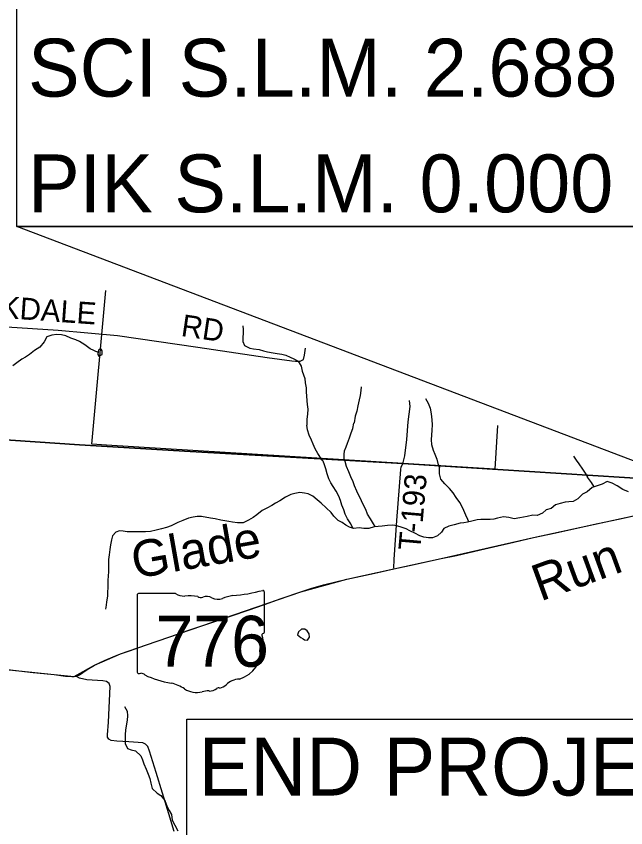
# Model space of a CAD drawing. Extents: x 0 to 40.8, y 0 to 22.
# Drawn here: x 5.177 to 6.756, y 16.222 to 18.326 of the extents above; entities that cross this region are included whole.
import ezdxf

# ---------------------------------------------------------------- set-up
doc = ezdxf.new("R2010")
doc.units = 0
for name, color, linetype in [('Default', 7, 'Continuous'), ('GM_X_County_Road', 7, 'Continuous'), ('GM_X_County_Road_Text', 7, 'Continuous'), ('GM_X_Minor_Lake', 7, 'Continuous'), ('GM_X_Minor_River', 7, 'Continuous'), ('GM_X_Minor_River_Text', 7, 'Continuous'), ('GM_X_Section', 7, 'Continuous'), ('GM_X_State_Location', 7, 'Continuous'), ('GM_X_State_Route', 7, 'Continuous'), ('GM_X_State_Shield', 7, 'Continuous'), ('GM_X_Township_Road', 7, 'Continuous'), ('GM_X_Township_Road_Text', 7, 'Continuous'), ('SH_Cut_Line', 7, 'Continuous')]:
    doc.layers.add(name, color=color, linetype=linetype)

msp = doc.modelspace()

# ---------------------------------------------------------------- linework, layer by layer
at = {"layer": 'Default'}
for points in [[(7.7204, 20.9), (3.6829, 20.9), (3.6703, 20.6733), (3.6672, 20.5588), (3.6386, 20.2396), (3.575, 19.3064), (3.5742, 19.2945), (3.5638, 19.132), (3.4481, 17.3334), (4.5348, 17.2687), (4.8294, 17.2493), (5.3407, 17.2146), (5.6278, 17.197), (6.1785, 17.166), (6.9172, 17.1197)], [(4.3506, 16.715), (5.2748, 16.619), (5.3265, 16.6142), (5.3792, 16.6434), (5.447, 16.6726), (5.5144, 16.6961), (5.9138, 16.8341), (6.0334, 16.8664), (6.155, 16.8931), (6.2776, 16.9198), (6.5168, 16.9746), (6.7757, 17.0304), (6.8501, 17.0497), (6.8977, 17.0853), (6.8977, 17.0853), (6.9174, 17.1192), (6.9291, 17.1755), (6.9382, 17.2349), (6.9766, 17.6024), (7.3436, 17.5605), (7.48, 17.5474)]]:
    msp.add_lwpolyline(points, dxfattribs=at)
for points in [[(5.1786, 18.9041), (6.7762, 18.9041), (6.7762, 17.7808), (5.1786, 17.7808)], [(6.7762, 17.7808), (6.9172, 17.1197), (5.1786, 17.7808)], [(2.1, 16.4387), (2.1, 14.1), (8.9, 14.1), (8.9, 16.9831), (7.7161, 17.0658), (7.7144, 17.066), (7.54, 17.0745), (7.4495, 17.0841), (6.9172, 17.1197), (6.1785, 17.166), (5.6278, 17.197), (5.3407, 17.2146), (4.8294, 17.2493), (4.5348, 17.2687), (3.4481, 17.3334), (3.1244, 17.3534), (2.8484, 17.3691), (2.8463, 17.3693), (2.4594, 17.3966), (2.4379, 17.0913), (2.3911, 16.4258)], [(5.6188, 16.5037), (6.9829, 16.5037), (6.9829, 15.6724), (5.6188, 15.6724)]]:
    msp.add_lwpolyline(points, close=True, dxfattribs=at)
at = {"layer": 'GM_X_County_Road'}
for points in [[(4.8531, 17.7162), (4.8463, 17.5982), (4.8448, 17.577), (4.8443, 17.5626), (4.8478, 17.5533), (4.8489, 17.5499), (4.8504, 17.5469), (4.8523, 17.5442), (4.855, 17.5415), (4.8599, 17.5377), (4.866, 17.535), (4.9121, 17.5364), (5.285, 17.5118), (5.4395, 17.4984), (5.6472, 17.4678), (5.8268, 17.441), (5.8904, 17.4325), (5.9002, 17.4317), (5.9067, 17.4313), (5.9128, 17.4316), (5.9208, 17.4358), (5.9239, 17.4468), (5.9261, 17.4652)], [(6.1787, 17.1655), (6.184, 17.1862), (6.1885, 17.2284), (6.1921, 17.2746), (6.1975, 17.314), (6.1953, 17.3293)], [(5.5855, 16.2123), (5.5718, 16.2585), (5.5392, 16.3655), (5.522, 16.4211), (5.518, 16.4327), (5.5117, 16.4392), (5.5046, 16.4425), (5.4684, 16.4449), (5.4371, 16.4469), (5.4228, 16.448), (5.4163, 16.4517), (5.4135, 16.4569), (5.4132, 16.4633), (5.4156, 16.4956), (5.4205, 16.5879), (5.4171, 16.5964), (5.4104, 16.601), (5.4007, 16.6033), (5.3593, 16.6059), (5.3409, 16.6099), (5.3315, 16.6151)]]:
    msp.add_lwpolyline(points, dxfattribs=at)
at = {"layer": 'GM_X_Minor_Lake'}
for points in [[(5.3883, 17.4487), (5.3905, 17.4449), (5.3943, 17.446), (5.3993, 17.449), (5.3993, 17.4581), (5.3967, 17.4623), (5.3925, 17.462), (5.3899, 17.4601), (5.3887, 17.4563)], [(5.3887, 17.4563), (5.3883, 17.4487)], [(5.9249, 16.7365), (5.9162, 16.7365), (5.9082, 16.7304), (5.9055, 16.7225), (5.9142, 16.7153), (5.9201, 16.7116)], [(5.9201, 16.7116), (5.9233, 16.7096), (5.9317, 16.708), (5.9366, 16.716), (5.9355, 16.7247), (5.9302, 16.7327), (5.9249, 16.7365)]]:
    msp.add_lwpolyline(points, dxfattribs=at)
at = {"layer": 'GM_X_Minor_River'}
for points in [[(5.7639, 17.5235), (5.765, 17.514), (5.765, 17.5034), (5.7638, 17.4939), (5.7641, 17.4829), (5.7682, 17.4723), (5.7818, 17.4654), (5.7916, 17.4634), (5.806, 17.4614), (5.8177, 17.4583), (5.8275, 17.456), (5.8423, 17.4529), (5.8525, 17.4513), (5.8649, 17.4493), (5.8755, 17.4474), (5.8861, 17.442), (5.8959, 17.4378), (5.9069, 17.4316), (5.9151, 17.4187), (5.9177, 17.4054), (5.9214, 17.3959), (5.9244, 17.3864), (5.9254, 17.375), (5.928, 17.3621), (5.9283, 17.3515), (5.929, 17.3413), (5.9293, 17.3291), (5.9304, 17.3189), (5.9322, 17.3071), (5.9318, 17.2946), (5.9298, 17.2813), (5.9293, 17.266)], [(5.3886, 17.4538), (5.3679, 17.4633), (5.3547, 17.4739), (5.3408, 17.4828), (5.331, 17.487), (5.3185, 17.4912), (5.3049, 17.497), (5.294, 17.4997), (5.2815, 17.5005), (5.2693, 17.4987), (5.2564, 17.4946), (5.2488, 17.4818), (5.2381, 17.4674), (5.224, 17.4592), (5.2107, 17.449), (5.2005, 17.4423), (5.191, 17.4366), (5.178, 17.4272), (5.1681, 17.4197)], [(6.0704, 17.3654), (6.0699, 17.3552), (6.068, 17.3423), (6.0656, 17.331), (6.0621, 17.3158), (6.0594, 17.3018), (6.0551, 17.2886), (6.0519, 17.272)], [(6.2375, 17.3345), (6.2439, 17.3227), (6.2491, 17.3094), (6.2517, 17.295), (6.2535, 17.2798), (6.2541, 17.2669), (6.2533, 17.2525), (6.2516, 17.2275), (6.2523, 17.2154), (6.2568, 17.2009), (6.2616, 17.1903), (6.2668, 17.1774), (6.2687, 17.166), (6.2737, 17.1555)], [(6.0286, 17.1711), (6.0268, 17.1783), (6.0264, 17.1893), (6.0276, 17.1988), (6.0314, 17.2098), (6.0352, 17.2193), (6.0405, 17.2329), (6.0447, 17.2454), (6.0489, 17.2572), (6.0512, 17.2705), (6.0519, 17.272)], [(5.9697, 17.1749), (5.9579, 17.1921), (5.9515, 17.2042), (5.9458, 17.2168), (5.942, 17.227), (5.936, 17.2395), (5.9311, 17.2532), (5.9293, 17.266)], [(6.6205, 17.1855), (6.6276, 17.1753), (6.6348, 17.1657), (6.6438, 17.1517), (6.6509, 17.1414), (6.6566, 17.1311)], [(6.0492, 16.9986), (6.044, 17.0103), (6.0353, 17.0229), (6.0293, 17.0354), (6.0258, 17.046), (6.0205, 17.0581), (6.0168, 17.0703), (6.0122, 17.0817), (6.0061, 17.0942), (5.9978, 17.1071), (5.9918, 17.1166), (5.9868, 17.1264), (5.9823, 17.1397), (5.9785, 17.1526), (5.9755, 17.1625), (5.9717, 17.172), (5.9697, 17.1749)], [(6.1067, 17.0026), (6.102, 17.0103), (6.0944, 17.0225), (6.0872, 17.035), (6.0823, 17.0475), (6.0743, 17.0631), (6.0683, 17.076), (6.0634, 17.0855), (6.0596, 17.0949), (6.0535, 17.1086), (6.0497, 17.1185), (6.0437, 17.1321), (6.0387, 17.145), (6.0323, 17.1583), (6.0286, 17.1711)], [(6.3494, 17.015), (6.3464, 17.0213), (6.3414, 17.0327), (6.3365, 17.0448), (6.3312, 17.0555), (6.3263, 17.065), (6.3164, 17.0779), (6.3085, 17.09), (6.299, 17.1018), (6.2876, 17.1139), (6.2767, 17.1257), (6.2736, 17.1393), (6.2737, 17.1555)], [(6.6745, 17.1061), (6.6669, 17.1173), (6.6566, 17.1311)], [(6.7631, 17.093), (6.7487, 17.0991), (6.7339, 17.1082), (6.7211, 17.1154), (6.7082, 17.1196), (6.6949, 17.1131), (6.682, 17.1086), (6.6692, 17.1044), (6.6563, 17.0926), (6.6442, 17.0869), (6.6316, 17.0744), (6.6199, 17.068), (6.6089, 17.0668), (6.5991, 17.0661), (6.5862, 17.0623), (6.5741, 17.0596), (6.5631, 17.0498), (6.5498, 17.046), (6.5403, 17.0373), (6.5263, 17.0319), (6.5153, 17.0323), (6.5006, 17.0293), (6.4911, 17.027), (6.4816, 17.0251), (6.4668, 17.0225), (6.4528, 17.0266), (6.4396, 17.0278), (6.424, 17.0244), (6.4142, 17.0221), (6.4043, 17.0209), (6.3808, 17.0209), (6.371, 17.0202), (6.3573, 17.0168), (6.3456, 17.0141), (6.3361, 17.0122), (6.3267, 17.0115), (6.3115, 17.0077), (6.2975, 17.0039), (6.285, 16.9982), (6.2785, 16.9883), (6.2683, 16.9792), (6.2554, 16.9735), (6.2452, 16.9739), (6.2327, 16.9758), (6.2228, 16.9792), (6.2096, 16.9861)], [(6.2096, 16.9861), (6.1967, 16.9917), (6.1872, 16.9971), (6.177, 17.0008), (6.1626, 17.005), (6.1524, 17.0065), (6.1391, 17.0058), (6.1247, 17.0039), (6.1141, 17.0031), (6.1043, 17.0024), (6.0902, 16.9978), (6.0777, 16.9982), (6.0649, 16.9997), (6.0505, 16.9982), (6.0406, 17.0012), (6.0311, 17.0069), (6.0209, 17.013), (6.0111, 17.0183), (5.9997, 17.0297), (5.9925, 17.0396), (5.98, 17.0517), (5.9664, 17.0638), (5.9565, 17.0722), (5.9455, 17.0817), (5.9334, 17.0874), (5.9236, 17.0896), (5.9118, 17.0912), (5.8982, 17.0885), (5.8883, 17.0862), (5.8743, 17.0794), (5.8599, 17.0699), (5.8485, 17.0631), (5.8391, 17.0578), (5.8258, 17.0502), (5.8141, 17.0449), (5.8004, 17.0335), (5.7906, 17.0263), (5.7781, 17.0191), (5.7644, 17.0126), (5.7504, 17.0126), (5.7371, 17.0145), (5.7277, 17.0164), (5.7174, 17.018), (5.7065, 17.0198), (5.6924, 17.0229), (5.6803, 17.0244), (5.6568, 17.029), (5.6451, 17.029), (5.6352, 17.0271), (5.6227, 17.0244), (5.6087, 17.0183), (5.5954, 17.0134), (5.578, 17.0047), (5.5663, 17.0005), (5.553, 16.9967), (5.5394, 16.9933), (5.5246, 16.9903), (5.5117, 16.9891), (5.464, 16.9891), (5.4537, 16.9907), (5.4443, 16.9918), (5.4344, 16.988), (5.4265, 16.9785), (5.4234, 16.9683), (5.4212, 16.9554), (5.4196, 16.9432), (5.4177, 16.9296), (5.4162, 16.9171), (5.4158, 16.9061), (5.4162, 16.8966), (5.4162, 16.8867), (5.4151, 16.8742), (5.4143, 16.8643), (5.4139, 16.8549), (5.4139, 16.845), (5.4136, 16.8329), (5.4128, 16.8222), (5.4109, 16.8082), (5.4098, 16.7987), (5.4083, 16.7885)], [(5.4575, 16.5362), (5.4643, 16.5248), (5.465, 16.5119), (5.4643, 16.5009), (5.4616, 16.4861), (5.4597, 16.4748), (5.459, 16.4638), (5.4593, 16.4543), (5.4593, 16.441), (5.465, 16.4277), (5.4745, 16.4243), (5.4859, 16.4216), (5.4999, 16.4084), (5.504, 16.3981), (5.5071, 16.3879), (5.5131, 16.3738), (5.5188, 16.3609), (5.523, 16.3503), (5.5256, 16.3374), (5.529, 16.3238), (5.5415, 16.3116), (5.551, 16.3056), (5.5616, 16.293), (5.5665, 16.2794), (5.5733, 16.2669), (5.5787, 16.2566), (5.5809, 16.2422), (5.5877, 16.2286), (5.5957, 16.2145)]]:
    msp.add_lwpolyline(points, dxfattribs=at)
at = {"layer": 'GM_X_Section'}
msp.add_lwpolyline([(6.4233, 17.265), (6.4168, 17.1516), (5.4109, 17.2138), (5.3726, 17.2161), (5.4091, 17.6151)], dxfattribs=at)
at = {"layer": 'GM_X_State_Route'}
msp.add_lwpolyline([(5.1541, 16.6323), (5.2209, 16.625), (5.2748, 16.619), (5.3041, 16.6155), (5.3206, 16.6139), (5.3265, 16.6142), (5.3315, 16.6151), (5.3358, 16.6164), (5.3408, 16.6189), (5.3606, 16.6323), (5.3792, 16.6434), (5.3923, 16.6499), (5.4053, 16.6556), (5.4277, 16.6648), (5.447, 16.6726), (5.47, 16.6808), (5.5144, 16.6961), (5.5748, 16.717), (5.6237, 16.734), (5.6913, 16.7564), (5.7316, 16.7702), (5.7799, 16.7871), (5.8204, 16.8011), (5.8631, 16.8164), (5.9138, 16.8341), (5.9424, 16.8436), (5.9732, 16.852), (6.0334, 16.8664), (6.1056, 16.8824), (6.155, 16.8931), (6.2076, 16.9046), (6.2776, 16.9198), (6.3176, 16.9282), (6.3907, 16.9449), (6.4662, 16.9626), (6.5168, 16.9746), (6.5749, 16.9868), (6.6719, 17.0082), (6.7495, 17.0246), (6.7757, 17.0304)], dxfattribs=at)
at = {"layer": 'GM_X_State_Shield'}
for p, q in [((5.5897, 16.8291), (5.4932, 16.8291)), ((5.8196, 16.7294), (5.8196, 16.8341)), ((5.49, 16.8257), (5.49, 16.6256)), ((5.8195, 16.7294), (5.8196, 16.7294))]:
    msp.add_line(p, q, dxfattribs=at)
for centre, major_axis, start_param, end_param in [((5.4938, 16.8261), (0.00382, 0), 1.712693, 3.28349), ((5.6127, 16.8523), (0.037, 0), 4.042523, 4.731795), ((5.7022, 17.102), (0.3495, 0), 4.814394, 5.042369), ((5.8159, 16.8345), (0.00367, 0), 6.141152, 7.989035), ((5.625, 16.7168), (0.133, 0), 1.404758, 1.657858), ((5.6552, 16.8271), (0.0107, 0), 3.836095, 5.185415), ((5.6709, 16.804), (0.0222, 0), 0.950623, 2.079405), ((5.6996, 16.8357), (0.0267, 0), 4.081561, 5.145723), ((5.7467, 16.768), (0.0703, 0), 1.699011, 2.107814), ((5.8187, 16.7217), (0.00568, 0), 1.883978, 3.671073), ((5.8157, 16.729), (0.00393, 0), 5.05454, 6.418171), ((5.7826, 16.7085), (0.0341, 0), 5.934695, 6.695948), ((5.7217, 16.6723), (0.0874, 0), 5.101752, 6.440018), ((5.8327, 16.6856), (0.0248, 0), 2.387724, 3.262537), ((5.4938, 16.6251), (0.00385, 0), 3.00124, 4.508301), ((5.4944, 16.6456), (0.0294, 0), 4.665946, 4.897461), ((5.5004, 16.614), (0.0106, 0), 0.519207, 1.627899), ((5.6342, 16.7938), (0.2524, 0), 4.195997, 4.488961), ((5.559, 16.5356), (0.079, 0), 0.823519, 1.323587), ((5.7586, 16.5694), (0.0479, 0), 1.647645, 2.488434), ((5.6444, 16.613), (0.0501, 0), 4.026481, 4.996735), ((5.6733, 16.5438), (0.0412, 0), 1.495662, 1.94098), ((5.677, 16.598), (0.0267, 0), 4.691044, 5.507374), ((5.7011, 16.5786), (0.00752, 0), 1.147584, 2.315152), ((5.6979, 16.6062), (0.0282, 0), 4.937069, 5.64225)]:
    msp.add_ellipse(centre, major_axis=major_axis, ratio=0.8, start_param=start_param, end_param=end_param, dxfattribs=at)
at = {"layer": 'GM_X_Township_Road'}
msp.add_lwpolyline([(6.155, 16.8953), (6.1556, 16.9172), (6.1625, 17.0185), (6.1734, 17.1507), (6.1742, 17.1581), (6.1787, 17.1655)], dxfattribs=at)
at = {"layer": 'SH_Cut_Line'}
for points in [[(7.7204, 20.9), (2.1, 20.9), (2.1, 17.4153), (2.4594, 17.3966), (2.8463, 17.3693), (2.8484, 17.3691), (3.1244, 17.3534), (3.4481, 17.3334), (4.5348, 17.2687), (4.8294, 17.2493), (5.3407, 17.2146), (5.6278, 17.197), (6.1785, 17.166), (6.9172, 17.1197), (7.4495, 17.0841), (7.4798, 17.5479), (7.4963, 17.9476), (7.5246, 18.2047), (7.5789, 18.8336), (7.595, 19.0259), (7.6007, 19.1025), (7.6007, 19.1071), (7.6192, 19.376), (7.7055, 20.511)], [(2.1, 17.4153), (2.1, 14.1), (8.9, 14.1), (8.9, 16.9831), (7.7161, 17.0658), (7.7144, 17.066), (7.54, 17.0745), (7.4495, 17.0841), (6.9172, 17.1197), (6.1785, 17.166), (5.6278, 17.197), (5.3407, 17.2146), (4.8294, 17.2493), (4.5348, 17.2687), (3.4481, 17.3334), (3.1244, 17.3534), (2.8484, 17.3691), (2.8463, 17.3693), (2.4594, 17.3966)]]:
    msp.add_lwpolyline(points, close=True, dxfattribs=at)

# ---------------------------------------------------------------- texts
at = {"layer": 'Default'}
for s, p in [('SCI S.L.M. 2.688', (5.2073, 18.1173)), ('PIK S.L.M. 0.000', (5.2073, 17.8173)), ('END PROJECT', (5.6493, 16.3057))]:
    msp.add_text(s, height=0.15, dxfattribs=at).set_placement(p)
at = {"layer": 'GM_X_County_Road_Text'}
for s, rotation, p in [('STOCKDALE', 355.9547, (4.9231, 17.5589)), ('RD', 351.5894, (5.6017, 17.497))]:
    msp.add_text(s, height=0.05682, rotation=rotation, dxfattribs=at).set_placement(p)
at = {"layer": 'GM_X_Minor_River_Text'}
for s, rotation, p in [('Glade', 9.9999, (5.4842, 16.8675)), ('Run', 20.0009, (6.5348, 16.8083))]:
    msp.add_text(s, height=0.09469, rotation=rotation, dxfattribs=at).set_placement(p)
at = {"layer": 'GM_X_State_Location'}
for s in ['s', 'r']:
    msp.add_text(s, height=0.000189, dxfattribs=at).set_placement((5.6511, 16.7123))
msp.add_text('776', height=0.000189, rotation=0, dxfattribs=at).set_placement((5.5842, 16.6985))
at = {"layer": 'GM_X_State_Shield'}
msp.add_text('776', height=0.13184, dxfattribs=at).set_placement((5.5374, 16.6397))
at = {"layer": 'GM_X_Township_Road_Text'}
msp.add_text('T-193', height=0.05682, rotation=84.9324, dxfattribs=at).set_placement((6.2233, 16.9393))

doc.saveas('drawing.dxf')
